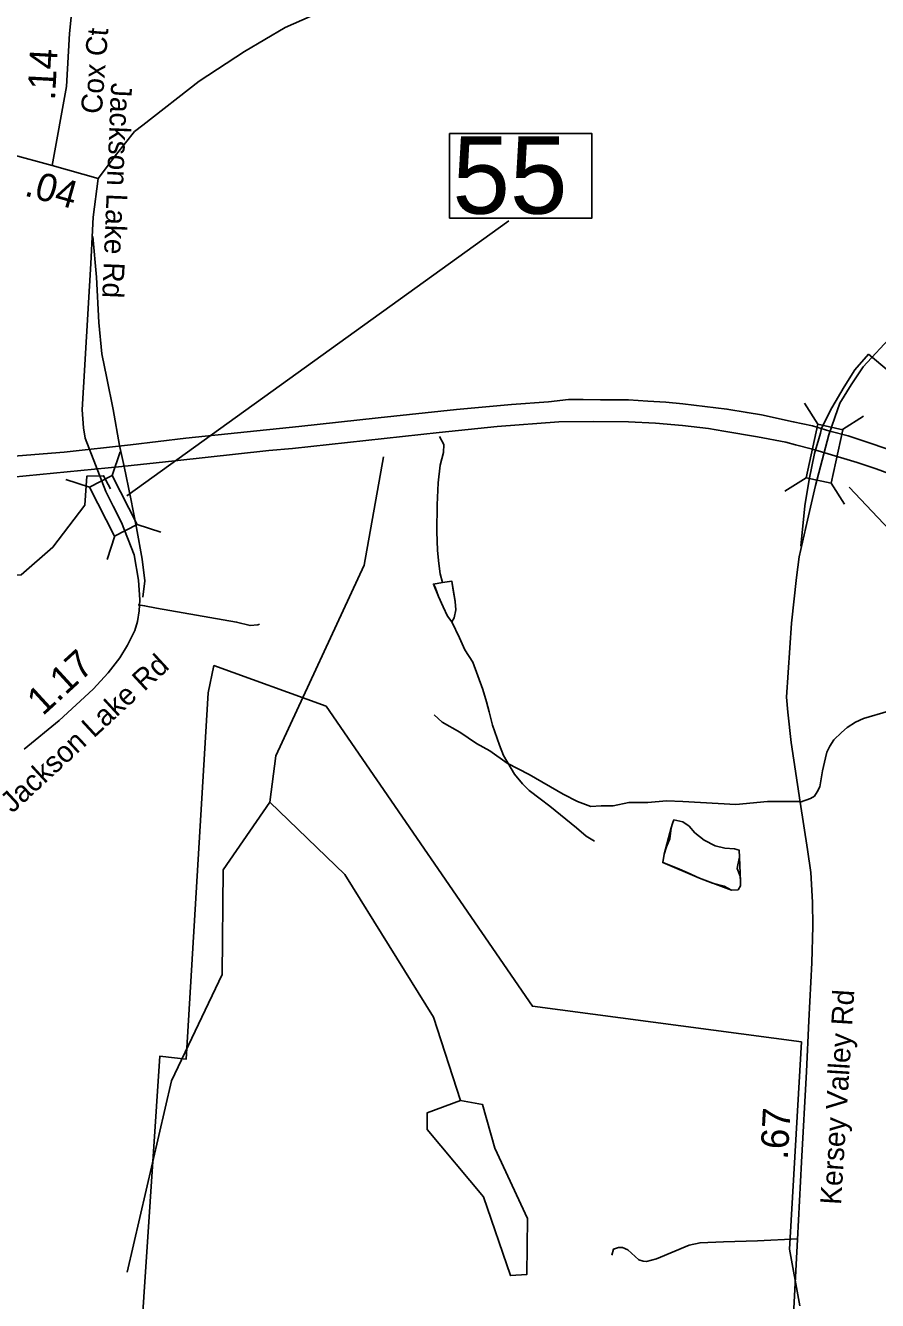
# Model space of a CAD drawing. Extents: x 1662474 to 1856135, y 779280 to 917889.
# Drawn here: x 1719166 to 1723021, y 793320 to 799088 of the extents above; entities that cross this region are included whole.
import ezdxf

# ---------------------------------------------------------------- set-up
doc = ezdxf.new("R2010")
doc.units = 0
for name, color, linetype in [('Exist Boundary Political City Limit New', 7, 'Continuous'), ('Exist Hydrographic Misc Water Feature', 7, 'Continuous'), ('Exist Hydrographic Pond Under 1500 Sq Ft', 7, 'Continuous'), ('Exist Road Non-System Type 51', 7, 'Continuous'), ('Exist Road Secondary Mileage Tenths English Label', 7, 'Continuous'), ('Exist Road Secondary Structure Standard Bridge CELL', 7, 'Continuous'), ('Exist Road Secondary Structure Standard Bridge Number Label', 7, 'Continuous'), ('Exist Road Secondary Type 51 Attributed', 7, 'Continuous'), ('Exist Road Secondary Type 51 Label', 7, 'Continuous'), ('Map Preparation Boundary City Limit Buffer Line', 7, 'Continuous'), ('Prop DGN Element Guardrail', 7, 'Continuous'), ('Prop Road Primary US Projected', 7, 'Continuous'), ('Prop Road Secondary Projected', 7, 'Continuous')]:
    doc.layers.add(name, color=color, linetype=linetype)

msp = doc.modelspace()

# ---------------------------------------------------------------- linework, layer by layer
at = {"layer": 'Exist Boundary Political City Limit New'}
for points in [[(1722677.8, 794489.6), (1721459.9, 794651.1), (1720526.5, 796008.1), (1720018.6, 796192.6), (1719993, 796068.7), (1719892.9, 794411.4), (1719773.5, 794425.2), (1719686.9, 793108.8), (1719689.8, 792716.2), (1719684.8, 792575.9), (1719648.6, 792342.6), (1719493.9, 792449.4), (1719321, 792584.1), (1719308, 792409), (1719161.8, 792412.2)], [(1722669.8, 793296), (1722622.8, 793552.2), (1722677.8, 794489.6)]]:
    msp.add_lwpolyline(points, dxfattribs=at)
at = {"layer": 'Exist Hydrographic Misc Water Feature'}
for points in [[(1721039.9, 797228.9), (1721059.3, 797192.7), (1721057.1, 797156.7), (1721042.5, 797098.8), (1721033.7, 797018.9), (1721029, 796918.9), (1721027.8, 796798.9), (1721030.8, 796712.8), (1721036.4, 796654.7), (1721041.9, 796606.7), (1721053.6, 796568.5)], [(1720271.3, 795575), (1720298.2, 795784.5), (1720698.2, 796646.3), (1720786.2, 797136.8)], [(1718622.3, 796567), (1718781.2, 796596.6), (1719147.2, 796602.3), (1719290.3, 796727.4), (1719434.3, 796918.1), (1719443.2, 797049.2), (1719519.3, 797051), (1719551.3, 796991.3)], [(1721095.6, 796389.9), (1721076.2, 796416.3), (1721056.5, 796458.5), (1721034.9, 796504.7), (1721019.4, 796546.9), (1721011.6, 796561), (1721053.6, 796568.5)], [(1721095.6, 796389.9), (1721076.2, 796416.3), (1721056.5, 796458.5), (1721034.9, 796504.7), (1721011.6, 796561), (1721053.6, 796568.5)], [(1721053.6, 796568.5), (1721095.6, 796574.2), (1721101.4, 796534.1), (1721110.8, 796482), (1721112.5, 796444), (1721106.1, 796408), (1721095.6, 796389.9)], [(1721053.6, 796568.5), (1721095.6, 796574.2), (1721110.8, 796482), (1721112.5, 796444), (1721106.1, 796408), (1721095.6, 796389.9)], [(1721095.6, 796389.9), (1721129.3, 796317.8), (1721154.7, 796263.5), (1721190.2, 796207.1), (1721235.1, 796084.7), (1721252.5, 796028.5), (1721264, 795982.4), (1721279.6, 795922.2), (1721310.7, 795831.9), (1721328.4, 795785.7), (1721379.4, 795701.2), (1721415.1, 795656.8), (1721444.8, 795626.6), (1721494.5, 795590.1), (1721538.1, 795555.7), (1721659.3, 795458.5), (1721703, 795420.1), (1721740.7, 795397.7)], [(1719626.2, 793448), (1719826.3, 794313.8), (1720056.2, 794794.9), (1720060.2, 795267.5), (1720271.3, 795575)], [(1721134.4, 794224.9), (1721012.4, 794601.5), (1720610.3, 795246.5), (1720271.3, 795575)], [(1722099.8, 795494.3), (1722139.8, 795486), (1722169.5, 795465.7), (1722195.1, 795435.5), (1722237, 795403), (1722286.8, 795376.6), (1722330.7, 795366.1), (1722374.5, 795363.7), (1722394.6, 795357.5), (1722396.3, 795325.5), (1722389.9, 795291.5), (1722385.6, 795273.6), (1722399.4, 795239.4), (1722401.2, 795215.5), (1722401, 795195.4), (1722390.7, 795177.5), (1722360.8, 795175.8), (1722327, 795194.1), (1722275.1, 795208.6), (1722215.2, 795231.2), (1722159.4, 795255.7), (1722125.6, 795272), (1722083.8, 795288.5), (1722049.7, 795300.8), (1722056.1, 795338.7), (1722066.6, 795372.6), (1722080.9, 795408.5), (1722087.3, 795458.4), (1722093.6, 795478.4), (1722099.8, 795494.3)], [(1722099.8, 795494.3), (1722139.8, 795486), (1722169.5, 795465.7), (1722195.1, 795435.5), (1722237, 795403), (1722286.8, 795376.6), (1722330.7, 795366.1), (1722374.5, 795363.7), (1722394.6, 795357.5), (1722396.3, 795325.5), (1722401.2, 795215.5), (1722401, 795195.4), (1722390.7, 795177.5), (1722360.8, 795175.8), (1722215.2, 795231.2), (1722049.7, 795300.8), (1722056.1, 795338.7), (1722087.3, 795458.4), (1722093.6, 795478.4), (1722099.8, 795494.3)]]:
    msp.add_lwpolyline(points, dxfattribs=at)
at = {"layer": 'Exist Hydrographic Pond Under 1500 Sq Ft'}
msp.add_lwpolyline([(1721134.4, 794224.9), (1720983.3, 794168.8), (1720983.3, 794093.4), (1721238.4, 793789.5), (1721360.4, 793432.5), (1721435.2, 793437.6), (1721437.3, 793690.2), (1721290.2, 794008.3), (1721234.3, 794206.4), (1721134.4, 794224.9)], dxfattribs=at)
at = {"layer": 'Exist Road Non-System Type 51'}
for points in [[(1719675.4, 796466.7), (1719705.1, 796462.8), (1719759.1, 796452.8), (1720121.1, 796388.8), (1720182.2, 796373.5), (1720217.6, 796376.2), (1720225.6, 796380.1)], [(1722669.1, 795577.8), (1722524.1, 795577.8), (1722379.4, 795563.6), (1722140.8, 795577.8), (1722066.5, 795579.9), (1721982, 795573.2), (1721895.6, 795572.5), (1721824.8, 795557.8), (1721770.6, 795557.8), (1721724.8, 795554.4), (1721664.1, 795577.8), (1721598.8, 795610.5), (1721444.6, 795699), (1721346.2, 795750.4), (1721267.2, 795806.6), (1721206.1, 795839.7), (1721131.4, 795890.9), (1721052.1, 795937), (1721014.5, 795970.1)], [(1722661.2, 793598.8), (1722478.9, 793589.1), (1722323.6, 793584.9), (1722218.4, 793580.9), (1722169.6, 793569.4), (1722021.4, 793508.5), (1721975.4, 793496.4), (1721960.4, 793498), (1721941.9, 793504.2), (1721891.1, 793548.9), (1721867.2, 793559.7), (1721848.9, 793560.2), (1721826.6, 793551.5), (1721818.4, 793524.8)]]:
    msp.add_lwpolyline(points, dxfattribs=at)
at = {"layer": 'Exist Road Secondary Structure Standard Bridge CELL'}
for p, q in [((1722751.8, 797284.4), (1722690.8, 797379.7)), ((1722862.3, 797260), (1722957.6, 797321)), ((1719593.8, 797159.5), (1719558.8, 797051.8)), ((1722602.6, 796981.4), (1722698, 797042.4)), ((1719348, 797034.3), (1719455.7, 796999.3)), ((1722872, 796922.1), (1722811.1, 797017.5)), ((1719670.9, 796830.7), (1719778.5, 796795.7)), ((1719570, 796779.3), (1719535, 796671.7))]:
    msp.add_line(p, q, dxfattribs=at)
for points in [[(1722698, 797042.4), (1722751.2, 797284.5), (1722864.3, 797259.6), (1722811.1, 797017.5)], [(1719558.8, 797051.8), (1719671.3, 796831), (1719568.2, 796778.4), (1719455.7, 796999.3)]]:
    msp.add_lwpolyline(points, close=True, dxfattribs=at)
at = {"layer": 'Exist Road Secondary Structure Standard Bridge Number Label'}
for p, q in [((1719624.9, 796960.8), (1721353.5, 798204.2)), ((1722892.7, 796999), (1724278.8, 795531.4))]:
    msp.add_line(p, q, dxfattribs=at)
msp.add_lwpolyline([(1721085, 798599.3), (1721729.1, 798599.3), (1721729.1, 798217), (1721085, 798217)], close=True, dxfattribs=at)
at = {"layer": 'Exist Road Secondary Type 51 Attributed'}
msp.add_line((1719495, 798396.1), (1719287, 798454.6), dxfattribs=at)
for points in [[(1719287, 798454.6), (1719352, 798811.8), (1719365, 799052.1), (1719384.5, 799247)], [(1720543.5, 799168.6), (1720341.6, 799079.6), (1720157.4, 798971.3), (1719951.6, 798836), (1719696.8, 798637.6), (1719659, 798608.6), (1719577.7, 798505.8), (1719495, 798396.1)], [(1719287, 798454.6), (1719098.5, 798506.5), (1718962, 798539), (1718841.8, 798579.5)], [(1719495, 798396.1), (1719472.4, 798221), (1719462, 798011.5), (1719422.6, 797348.8), (1719428.5, 797268.6), (1719435.4, 797221.5), (1719529.4, 796979.2), (1719563, 796913.3)], [(1722671.2, 795573.8), (1722630.7, 795844), (1722614.9, 795982.1), (1722609.5, 796049.1), (1722632.2, 796383.7), (1722653.9, 796590.1), (1722667.4, 796684.9), (1722704.3, 796850.2), (1722741.3, 797006.5), (1722800.9, 797236.7), (1722828, 797315.4), (1722850.2, 797379.4), (1722901.9, 797463.1), (1722956, 797544.3), (1723090.4, 797688.5)], [(1719563, 796913.3), (1719601.1, 796839.4), (1719658.4, 796692.9), (1719677.5, 796578.3), (1719683.9, 796489.2), (1719680.4, 796440.6), (1719672.8, 796391.4), (1719660.2, 796351.1), (1719628, 796284.9), (1719593.4, 796227.6), (1719539.7, 796158.9), (1719471.6, 796085.8), (1719317.8, 795944.6), (1719160.3, 795813.6)], [(1722671.2, 795573.8), (1722717.5, 795590.5), (1722735.6, 795601.9), (1722748.6, 795620.7), (1722760, 795644.2), (1722772.1, 795716.6), (1722785.2, 795775.6), (1722792.6, 795800.4), (1722805.3, 795827.2), (1722823.4, 795856.7), (1722857.9, 795890.2), (1722883.4, 795912.3), (1722920.9, 795936.5), (1722957.8, 795952.6), (1723070.8, 795986.1)], [(1722639.4, 793227.4), (1722658.8, 793596.1), (1722676.9, 793945.4), (1722700.4, 794356.3), (1722709.8, 794585.5), (1722724.4, 794847.9), (1722729.2, 795013.1), (1722727.2, 795122.6), (1722719.8, 795256.7), (1722705.1, 795360.6), (1722671.2, 795573.8)]]:
    msp.add_lwpolyline(points, dxfattribs=at)
at = {"layer": 'Map Preparation Boundary City Limit Buffer Line'}
for points in [[(1722677.8, 794489.6), (1721459.9, 794651.1), (1720526.5, 796008.1), (1720018.6, 796192.6), (1719993, 796068.7), (1719892.9, 794411.4), (1719773.5, 794425.2), (1719686.9, 793108.8), (1719689.8, 792716.2), (1719684.8, 792575.9), (1719648.6, 792342.6), (1719493.9, 792449.4), (1719321, 792584.1), (1719308, 792409), (1719161.8, 792412.2)], [(1722669.8, 793296), (1722622.8, 793552.2), (1722677.8, 794489.6)]]:
    msp.add_lwpolyline(points, dxfattribs=at)
at = {"layer": 'Prop Road Primary US Projected'}
for points in [[(1719094.9, 797138), (1719340.4, 797158.1), (1719641.1, 797190.7), (1719891.7, 797220.7), (1720402.9, 797273.3), (1720761.2, 797313.4), (1721117, 797351), (1721365.1, 797373.6), (1721532.9, 797386.1), (1721623.1, 797396.1), (1721690.1, 797395.7), (1721768.1, 797394.9), (1721831.6, 797394.9), (1721894.3, 797394.1), (1721981.6, 797389), (1722063, 797383.9), (1722140.9, 797376.3), (1722340, 797352.5), (1722430.7, 797337.3), (1722496.8, 797326.3), (1722640, 797295.8), (1722726.4, 797277.1), (1722805.2, 797252.5)], [(1719601.5, 797092.7), (1719841.4, 797118.7), (1720267.8, 797166.1), (1720374.7, 797175.2), (1721038, 797247.1), (1721300.9, 797274.6), (1721579, 797294.4), (1721734.9, 797296), (1721893.8, 797294.4), (1722016.1, 797289.8), (1722138.3, 797279.2), (1722256, 797265.4), (1722326.3, 797253.2), (1722478.8, 797227.1), (1722607, 797203.1), (1722650.5, 797191.6), (1722727.1, 797171), (1722783.2, 797155)], [(1722805.2, 797252.5), (1722888.2, 797231.4), (1723001.4, 797194.5), (1723079.3, 797167.4), (1723181, 797130.1), (1723372.5, 797045.4), (1723514.8, 796974.2), (1723614.8, 796920), (1723765.6, 796835.2), (1723904.6, 796745.4), (1724038.5, 796652.2), (1724155.4, 796562.4)], [(1722783.2, 797155), (1722928.5, 797111.5), (1723015.4, 797082.9), (1723101.8, 797050.4), (1723269.7, 796977.1), (1723418.1, 796907), (1723515.9, 796861.3), (1723597.4, 796815.7), (1723759.8, 796718), (1723958.6, 796581.1), (1724166.2, 796426.5), (1724431.2, 796205.6), (1724766.9, 795905.3), (1725186.5, 795498.9), (1725385.3, 795295.7)], [(1719107.8, 797045.3), (1719601.5, 797092.7)]]:
    msp.add_lwpolyline(points, dxfattribs=at)
at = {"layer": 'Prop Road Secondary Projected'}
msp.add_line((1719612.9, 797093.5), (1719590.7, 797187.8), dxfattribs=at)
for points in [[(1719590.7, 797187.8), (1719563, 797350.6), (1719533.4, 797493.1), (1719511.2, 797602.2), (1719498.2, 797744.7), (1719487.1, 797950.1), (1719470.5, 798133.2)], [(1722768.5, 797265.9), (1722813.9, 797358.7), (1722870.7, 797453.4), (1722918.1, 797531), (1722980.6, 797601.1)], [(1722980.6, 797601.1), (1723154.8, 797455.3), (1723276, 797354.9), (1723571.4, 797112.6), (1723664.2, 797044.4), (1723738, 796987.6), (1723794.8, 796957.3), (1723851.6, 796932.7), (1723955.8, 796889.1), (1724037.2, 796866.4), (1724148.9, 796843.7), (1724264.4, 796836.1), (1724368.6, 796838), (1724489.8, 796855), (1724777.6, 796904.3)], [(1722673.8, 796732), (1722692.7, 796915.6), (1722711.7, 797034.9), (1722736.3, 797152.3), (1722762.8, 797243.2), (1722768.5, 797265.9)], [(1719697.7, 796501.4), (1719705.5, 796575.4), (1719694.4, 796673.5), (1719668.5, 796815.9), (1719640.7, 796954.7), (1719612.9, 797093.5)]]:
    msp.add_lwpolyline(points, dxfattribs=at)

# ---------------------------------------------------------------- texts
at = {"layer": 'Exist Road Secondary Mileage Tenths English Label'}
msp.add_text('.14', height=125, rotation=86.90364, dxfattribs=at).set_placement((1719299.3, 798747.9))
at = {"layer": 'Exist Road Secondary Structure Standard Bridge Number Label'}
msp.add_text('55', height=350, dxfattribs=at).set_placement((1721097.6, 798236.8))
at = {"layer": 'Exist Road Secondary Type 51 Label'}
for s, rotation, p in [('Cox Ct', 85.51334, (1719510.9, 798685.9)), ('Jackson Lake Rd', 267.62378, (1719553.9, 798830.2)), ('Jackson Lake Rd', 42.71946, (1719106.4, 795521.4)), ('Kersey Valley Rd', 86.43378, (1722855.9, 793750.9))]:
    msp.add_text(s, height=95, rotation=rotation, dxfattribs=at).set_placement(p)
at = {"layer": 'Prop DGN Element Guardrail'}
for s, rotation, p in [('.04', 344.30281, (1719156.3, 798320.2)), ('1.17', 42.53157, (1719244.3, 795962)), ('.67', 86.73217, (1722614.9, 793955.4))]:
    msp.add_text(s, height=125, rotation=rotation, dxfattribs=at).set_placement(p)

doc.saveas('drawing.dxf')
